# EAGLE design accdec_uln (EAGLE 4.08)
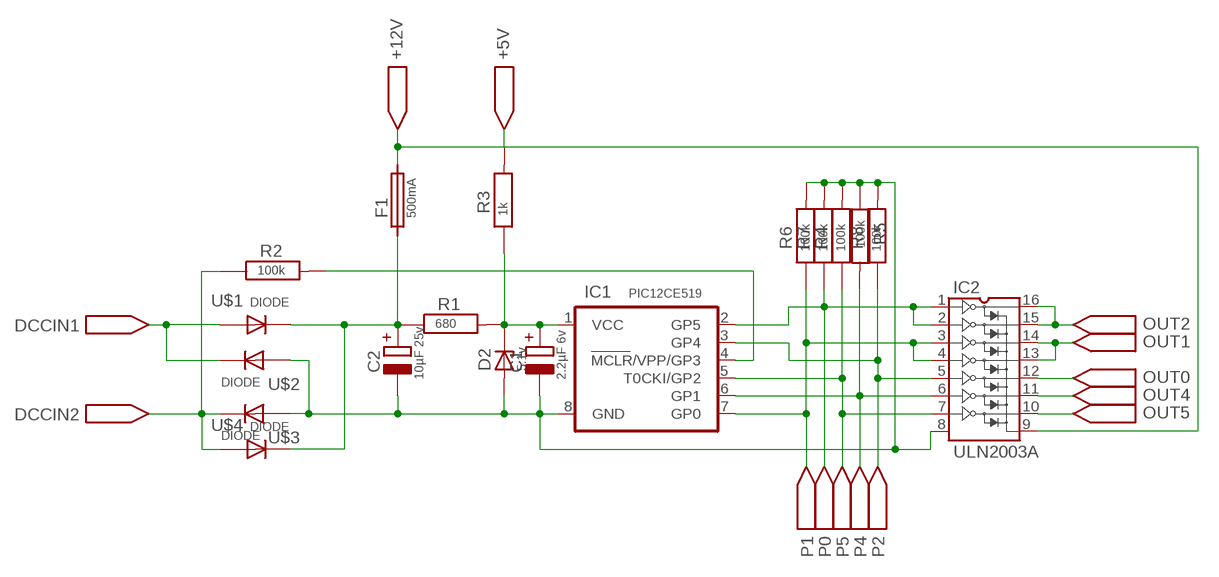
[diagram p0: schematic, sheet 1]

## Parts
+5V  PORT1*0.6  [CON_1*0.6]
+12V  PORT1.2*0.8  [CON_1.2*0.8]
C1  2.2µF 6v  ELKO_A  [CA]
C2  10µF 25v  ELKO_C  [CC]
D2  5.1v  ZMM  [ZMM]
DCCIN1  PORT1*0.6  [CON_1*0.6]
DCCIN2  PORT1*0.6  [CON_1*0.6]
F1  500mA  FUSE  [1210]
IC1  PIC12CE519  PIC12CE519/SN  [SO8/SN]
IC2  ULN2003A  ULN2001A  [SO16]
OUT0  PORT1*0.6  [CON_1*0.6]
OUT1  PORT1*0.6  [CON_1*0.6]
OUT2  PORT1*0.6  [CON_1*0.6]
OUT4  PORT1*0.6  [CON_1*0.6]
OUT5  PORT1*0.6  [CON_1*0.6]
P0  PORT1*0.6  [CON_1*0.6]
P1  PORT1*0.6  [CON_1*0.6]
P2  PORT1*0.6  [CON_1*0.6]
P4  PORT1*0.6  [CON_1*0.6]
P5  PORT1*0.6  [CON_1*0.6]
R1  680  R-M1  [MICRO_MELF]
R2  100k  R-M1  [MICRO_MELF]
R3  1k  R-M1  [MICRO_MELF]
R4  100k  R-M1  [MICRO_MELF]
R5  100k  R-M1  [MICRO_MELF]
R6  100k  R-M1  [MICRO_MELF]
R7  100k  R-M1  [MICRO_MELF]
R8  100k  R-M1  [MICRO_MELF]
U$1  DIODE  [1210D]
U$2  DIODE  [1210D]
U$3  DIODE  [1210D]
U$4  DIODE  [1210D]

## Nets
DCCIN: IC1.4(MCLR/VPP/GP3) R2.P$2
GND: C1.P$1(-) C2.P$1(-) D2.P$1(A) IC1.8(GND) IC2.8(GND) R4.P$2 R5.P$1 R6.P$2 R7.P$2 R8.P$2 U$2.1(A) U$3.1(A)
GP0: IC1.7(GP0) IC2.3(IN3) IC2.4(IN4) P1.P$1 R6.P$1
GP1: IC1.6(GP1) IC2.6(IN6) P4.P$1 R5.P$2
GP2: IC1.5(T0CKI/GP2) IC2.7(IN7) P5.P$1 R4.P$1
GP4: IC1.3(GP4) IC2.5(IN5) P2.P$1 R8.P$1
GP5: IC1.2(GP5) IC2.1(IN1) IC2.2(IN2) P0.P$1 R7.P$1
N$1: DCCIN1.P$1 U$1.1(A) U$2.2(K)
N$2: DCCIN2.P$1 R2.P$1 U$3.2(K) U$4.1(A)
N$3: +5V.P$1 R3.P$2
N$4: +12V.P$1 F1.2 IC2.9(COM)
N$5: C2.P$2(+) F1.1 R1.P$1 U$1.2(K) U$4.2(K)
N$10: IC2.12(OUT5) OUT0.P$1
N$11: IC2.11(OUT6) OUT4.P$1
N$12: IC2.10(OUT7) OUT5.P$1
N$13: IC2.15(OUT2) IC2.16(OUT1) OUT2.P$1
N$14: IC2.13(OUT4) IC2.14(OUT3) OUT1.P$1
VCC: C1.P$2(+) D2.P$2(K) IC1.1(VCC) R1.P$2 R3.P$1

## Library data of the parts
+5V +12V DCCIN1 DCCIN2 OUT0 OUT1 OUT2 OUT4 OUT5 P0 P1 P2 P4 P5 = NMRA-DCC_Decoder_Parts:PORT
C1 C2 = NMRA-DCC_Decoder_Parts:ELKO
D2 = NMRA-DCC_Decoder_Parts:ZMM: DIODE
F1 = NMRA-DCC_Decoder_Parts:FUSE
IC1 = NMRA-DCC_Decoder_Parts:PIC12C*?: PIC12Cx5xx 8 bit Microchip Microcontroller with 2k byte PROM and 16 byte EEPROM
IC2 = NMRA-DCC_Decoder_Parts:UL
R1-R8 = NMRA-DCC_Decoder_Parts:R-: Resistor
U$1-U$4 = NMRA-DCC_Decoder_Parts:DIODE

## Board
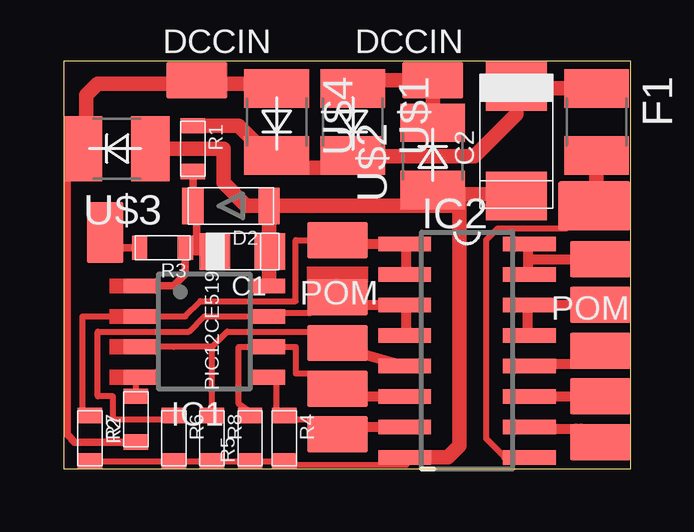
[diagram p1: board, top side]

Size 23.64 x 16.98 mm. Coordinates in mm from the lower left corner, seen from the top.
Outline: 0,0 23.64,0 23.64,16.98 0,16.98 0,0
Copper layers used: Top

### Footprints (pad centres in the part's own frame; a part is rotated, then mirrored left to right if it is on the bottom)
CON_1*0.6 = smd 2.54 x 1.524: P$1 0,0
CON_1.2*0.8 = smd 3.048 x 2.032: P$1 0,0
CA = smd 1.27 x 1.524: P$1 -1.143,0; P$2 1.143,0
CC = smd 2.032 x 2.54: P$1 -2.286,0; P$2 2.286,0
ZMM = smd 0.889 x 1.524: P$1 -1.587,0; P$2 1.587,0
1210 = smd 1.6 x 2.7: 1 -1.4,0; 2 1.4,0
SO8/SN = smd 0.61 x 1.524: 1 -1.905,-2.6; 2 -0.635,-2.6; 3 0.635,-2.6; 4 1.905,-2.6; 5 1.905,2.6; 6 0.635,2.6; 7 -0.635,2.6; 8 -1.905,2.6
SO16 = smd 0.6 x 2.2: 1 -4.445,-2.6; 2 -3.175,-2.6; 3 -1.905,-2.6; 4 -0.635,-2.6; 5 0.635,-2.6; 6 1.905,-2.6; 7 3.175,-2.6; 8 4.445,-2.6; 9 4.445,2.6; 10 3.175,2.6; 11 1.905,2.6; 12 0.635,2.6; 13 -0.635,2.6; 14 -1.905,2.6; 15 -3.175,2.6; 16 -4.445,2.6
MICRO_MELF = smd 0.635 x 1.016: P$1 -0.953,0; P$2 0.953,0
1210D = smd 1.6 x 2.7: 1 -1.4,0; 2 1.4,0

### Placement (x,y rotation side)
+5V  1.74,9.84 270 top
+12V  22.14,10.95 0 top
C1  7.46,9.04 180 top
C2  18.89,13.65 90 top
D2  6.98,10.95 180 top
DCCIN1  15.39,16.19 180 top
DCCIN2  5.55,16.19 180 top
F1  22.22,14.44 270 top
IC1  5.87,5.71 270 top
IC2  16.82,4.92 270 top
OUT0  22.38,4.92 0 top
OUT1  22.38,6.82 0 top
OUT2  22.38,8.73 0 top
OUT4  22.38,3.01 0 top
OUT5  22.38,1.11 0 top
P0  11.42,9.52 0 top
P1  11.42,7.14 180 top
P2  11.42,5.23 0 top
P4  11.42,3.33 0 top
P5  11.42,1.42 0 top
R1  5.39,13.33 270 top
R2  3.01,2.06 90 top
R3  4.12,9.2 180 top
R4  9.2,1.27 270 top
R5  7.77,1.26 90 top
R6  4.6,1.27 270 top
R7  1.11,1.27 270 top
R8  6.18,1.27 270 top
U$1  12.06,14.44 270 top
U$2  15.39,13.01 90 top
U$3  2.22,13.33 180 top
U$4  8.88,14.44 270 top

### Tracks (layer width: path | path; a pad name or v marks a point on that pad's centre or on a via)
DCCIN
  Top 0.254: IC1.4 | IC1.4 3.01,3.81 R2.P$2 | IC1.4
GND
  Top 0.254: R7.P$2 4.44,0.31 | 4.44,0.31 R6.P$2 4.44,0.31 | 4.44,0.31 R8.P$2 | R4.P$2 9.2,0.15 9.36,0.15 | R5.P$1 | R8.P$2 | R8.P$2 R5.P$1 | R4.P$2 | R4.P$2 | R5.P$1 | R5.P$1 R4.P$2 | 14.28,0.31 14.28,0.15 14.12,0.15 | 14.28,0.31 14.28,0.41 IC2.8 | R5.P$1 R4.P$2 | R4.P$2 9.36,0.15 | 9.36,0.15 14.12,0.15 | 14.12,0.15 14.28,0.31 | 14.28,0.31 14.44,0.47 | 8.57,7.62 | IC1.8 8.57,7.62 | C2.P$1 18.88,11.43
  Top 0.305: IC2.8 14.12,0.47 | 8.41,7.62 | IC1.8 8.41,7.62
  Top 0.406: C1.P$1 8.6,8.76 8.57,8.73
  Top 0.61: U$3.1 6.66,13.33 6.66,11.9 7.61,10.95 D2.P$1 | 8.57,8.73 D2.P$1 | 14.44,0.47 16.03,0.47 16.5,0.95 16.5,10.95 | D2.P$1 8.57,9.2 | 8.57,7.77 8.57,7.62 | IC1.8 8.47,7.68 8.57,7.77 | 8.57,9.2 8.6,9.17 C1.P$1 | 8.57,9.2 8.57,7.77 | D2.P$1 | D2.P$1 | 15.08,10.95 D2.P$1 | 16.5,10.95 15.08,10.95 | 15.39,11.27 | 15.39,11.27 U$2.1 | 15.08,10.95 15.39,11.27 | 18.88,11.43 16.5,11.43 16.5,10.95
GP0
  Top 0.254: 11.42,6.82 P1.P$1 10.31,6.5 9.04,6.5 IC1.7 5.87,6.35 5.23,5.71 1.42,5.71 1.42,3.01 2.06,3.01 2.06,2.06 4.44,2.06 R6.P$1
  Top 0.406: 11.42,6.82 IC2.3 14.28,6.82 14.28,5.55 IC2.4
GP1
  Top 0.254: P4.P$1 10.79,3.96 9.68,3.96 9.68,5.08 IC1.6 7.3,5.08 7.3,2.69 7.77,2.38 R5.P$2
  Top 0.406: P4.P$1 11.42,3.01 IC2.6
GP2
  Top 0.203: IC2.7 14.28,1.74 14.22,1.8
  Top 0.254: P5.P$1 10.31,2.06 9.52,2.06 | 10.63,1.74 10.31,2.06 9.52,2.06 | 9.52,2.06 9.2,2.38 R4.P$1 8.88,2.22 8.88,3.81 IC1.5 8.41,3.81
  Top 0.406: 10.63,1.74 IC2.7
GP4
  Top 0.254: 11.42,5.55 P2.P$1 10.95,5.71 6.82,5.71 6.18,5.08 | IC1.3 3.49,5.08 4.6,5.08 | 6.18,5.08 4.6,5.08 | IC1.3 | 4.6,5.08 IC1.3 | R8.P$1 6.18,5.08
  Top 0.406: IC2.5 11.42,5.08 11.42,5.55
GP5
  Top 0.254: 11.42,9.36 P0.P$1 9.68,9.52 9.68,6.98 5.71,6.98 5.07,6.35 3.49,6.35 IC1.2 | IC1.2 | IC1.2 0.79,6.35 0.79,2.38 1.11,2.38 R7.P$1
  Top 0.406: 11.42,9.36 IC2.1 14.28,9.36 14.28,8.09 IC2.2
N$1
  Top 0.305: U$1.1 12.06,16.19 | DCCIN1.P$1 | DCCIN1.P$1
  Top 0.61: 12.06,16.19 DCCIN1.P$1 U$2.2
N$2
  Top 0.254: 4.91,16.03 4.91,16.19 DCCIN2.P$1 5.55,16.03 | 8.38,16.03 U$4.1
  Top 0.305: U$3.2 0.82,13.46 0.95,12.85 0.15,12.06 0.15,1.42 0.47,1.11 R2.P$1
  Top 0.61: 0.95,12.85 U$3.2 | 0.95,12.85 | 4.91,16.03 5.55,16.03 | 5.55,16.03 8.38,16.03 | 5.55,16.03 1.42,16.03 0.95,15.55 0.95,12.85
N$3
  Top 0.305: +5V.P$1 1.9,9.68 1.9,9.2 R3.P$2
N$4
  Top 0.254: 22.22,11.27 20.95,10 18.09,10 17.62,9.52 17.62,1.27 18.41,0.47
  Top 0.305: +12V.P$1 22.22,11.27 | 18.41,0.47 IC2.9
  Top 0.61: 22.22,11.27 F1.2
N$5
  Top 0.305: U$1.2 12.56,12.57 12.53,12.54 | 18.91,15.84 18.88,16.19 18.88,15.87 18.89,15.87 C2.P$2 | 12.53,12.54 | 12.53,12.54 12.69,13.01
  Top 0.61: 18.91,15.84 F1.1 | R1.P$1 7.3,14.28 8.57,13.01 8.59,13.04 U$4.2 8.73,13.01 8.57,12.85 8.73,12.54 12.53,12.54 | 12.69,13.01 17.14,13.01 18.88,14.76 18.88,15.87
N$10
  Top 0.406: OUT0.P$1 21.38,4.38 20.11,4.38 IC2.12 19.36,4.28
N$11
  Top 0.406: IC2.11 OUT4.P$1
N$12
  Top 0.203: OUT5.P$1 22.22,1.11 21.58,1.66
  Top 0.406: IC2.10 20.25,1.66 21.36,1.66 OUT5.P$1 21.58,1.58 21.58,1.66
N$13
  Top 0.406: IC2.16 19.36,9.36 19.36,8.73 | 19.36,8.25 19.36,8.09 IC2.15 19.36,8.25 | 19.36,8.73 OUT2.P$1 | 19.36,8.73 19.36,8.25
N$14
  Top 0.406: OUT1.P$1 IC2.14 19.36,6.82 19.36,5.55 IC2.13
VCC
  Top 0.305: 5.55,9.04 C1.P$2 6.34,9.04 | 5.55,9.04 4.91,9.04 | 5.55,11.11 | 5.55,11.11 | 5.55,9.04 5.55,11.11 | 5.55,11.11 | 5.55,11.11 5.39,11.27 R1.P$2 | 5.55,11.11 D2.P$2 | 5.55,11.11 | 6.34,9.04 R3.P$1 5.07,8.09 4.6,7.62 3.33,7.62 | 6.34,9.04 | 3.33,7.62 | IC1.1 3.33,7.62
(copper drawn outside any net)
  shapes: Top area x5

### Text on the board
tPlace: DCCIN | DCCIN | POM | POM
